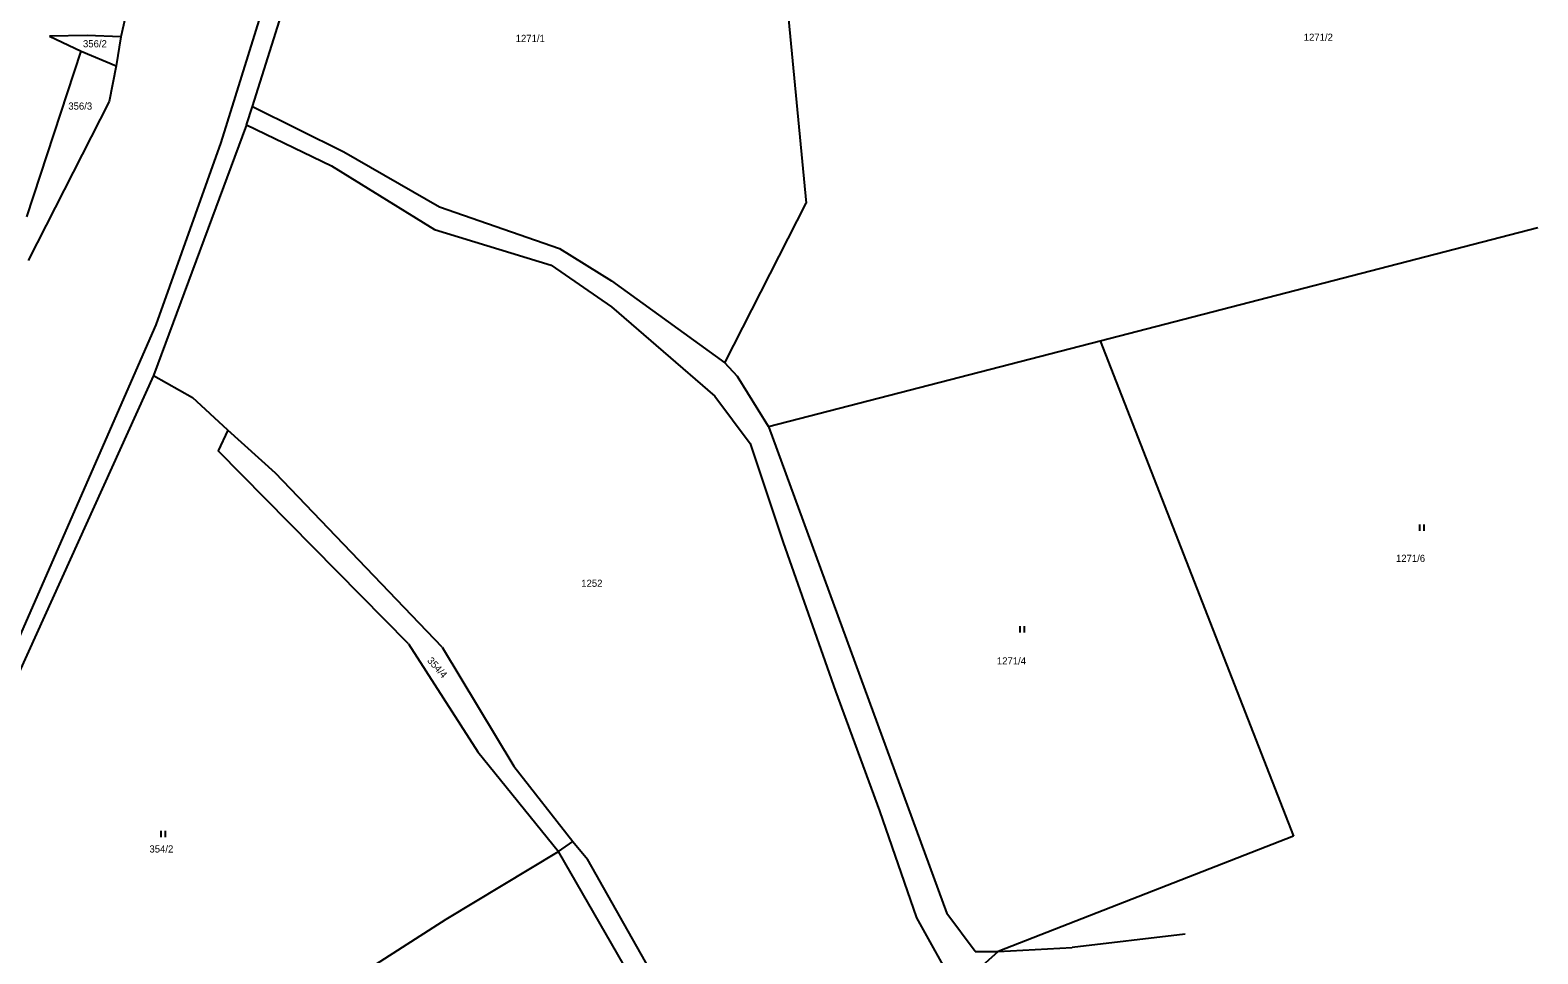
# Model space of a CAD drawing. Extents: x -717507 to -715515, y -957700 to -954941.
# Drawn here: x -716853.4 to -716494, y -957267.1 to -957047 of the extents above; entities that cross this region are included whole.
import ezdxf

# ---------------------------------------------------------------- set-up
doc = ezdxf.new("R2010")
doc.units = 0
for name, color, linetype in [('Hranice parcel', 7, 'Continuous'), ('Parcelní čísla', 7, 'Continuous'), ('Vnitřní kresba', 7, 'Continuous'), ('Značky kultur', 7, 'Continuous')]:
    doc.layers.add(name, color=color, linetype=linetype)

msp = doc.modelspace()

# ---------------------------------------------------------------- linework, layer by layer
at = {"layer": 'Hranice parcel'}
for points in [[(-716678.56, -956982.31), (-716668.42, -957088.24)], [(-716821.44, -957003.26), (-716831.73, -957048.65)], [(-716807.86, -957073.78), (-716793.1, -957026.3)], [(-716800.35, -957065.24), (-716789.3, -957030.13)], [(-716839.78, -957048.32), (-716848.77, -957048.44)], [(-716848.77, -957048.44), (-716841.23, -957052.04)], [(-716831.73, -957048.65), (-716839.78, -957048.32)], [(-716831.73, -957048.65), (-716832.89, -957055.51)], [(-716854.19, -957091.5), (-716841.23, -957052.04)], [(-716841.23, -957052.04), (-716832.89, -957055.51)], [(-716832.89, -957055.51), (-716834.54, -957064.04)], [(-716834.54, -957064.04), (-716853.87, -957101.91)], [(-716801.82, -957069.6), (-716800.35, -957065.24)], [(-716800.35, -957065.24), (-716778.59, -957076.02)], [(-716801.82, -957069.6), (-716823.97, -957129.29)], [(-716801.82, -957069.6), (-716781.58, -957079.38)], [(-716823.29, -957117.25), (-716807.86, -957073.78)], [(-716778.59, -957076.02), (-716755.82, -957089.14)], [(-716781.58, -957079.38), (-716757.02, -957094.51)], [(-716755.82, -957089.14), (-716727.24, -957099.03)], [(-716687.81, -957126.29), (-716668.42, -957088.24)], [(-716598.36, -957121.02), (-716494.03, -957094.01)], [(-716757.02, -957094.51), (-716729.16, -957103.06)], [(-716727.24, -957099.03), (-716714.82, -957106.72)], [(-716729.16, -957103.06), (-716714.79, -957112.95)], [(-716714.82, -957106.72), (-716687.81, -957126.29)], [(-716714.79, -957112.95), (-716690.17, -957134.23)], [(-716859.27, -957199.3), (-716823.29, -957117.25)], [(-716677.38, -957141.48), (-716598.36, -957121.02)], [(-716598.36, -957121.02), (-716552.25, -957239.06)], [(-716684.74, -957129.55), (-716687.81, -957126.29)], [(-716823.97, -957129.29), (-716857.93, -957204.39)], [(-716823.97, -957129.29), (-716814.69, -957134.59)], [(-716677.38, -957141.48), (-716684.74, -957129.55)], [(-716806.21, -957142.34), (-716814.69, -957134.59)], [(-716690.17, -957134.23), (-716681.72, -957145.53)], [(-716806.21, -957142.34), (-716808.59, -957147.29)], [(-716794.9, -957152.6), (-716806.21, -957142.34)], [(-716677.38, -957141.48), (-716634.86, -957257.48)], [(-716763.19, -957193.25), (-716808.59, -957147.29)], [(-716681.72, -957145.53), (-716673.91, -957169.1)], [(-716755.14, -957194.04), (-716794.9, -957152.6)], [(-716673.91, -957169.1), (-716661.46, -957204.5)], [(-716763.19, -957193.25), (-716746.65, -957219.01)], [(-716755.14, -957194.04), (-716738.11, -957222.42)], [(-716661.46, -957204.5), (-716650.97, -957233.01)], [(-716746.65, -957219.01), (-716727.45, -957242.7)], [(-716738.11, -957222.42), (-716724.03, -957240.38)], [(-716650.97, -957233.01), (-716642.15, -957258.58)], [(-716727.45, -957242.7), (-716724.03, -957240.38)], [(-716724.03, -957240.38), (-716720.49, -957244.6)], [(-716552.25, -957239.06), (-716622.66, -957266.55)], [(-716754.18, -957258.88), (-716727.45, -957242.7)], [(-716692.24, -957303.82), (-716727.45, -957242.7)], [(-716688.33, -957301.5), (-716720.49, -957244.6)], [(-716847.23, -957318.53), (-716754.18, -957258.88)], [(-716642.15, -957258.58), (-716632.66, -957275.53)], [(-716628.14, -957266.59), (-716634.86, -957257.48)], [(-716578.12, -957262.45), (-716605.01, -957265.65)], [(-716628.14, -957266.59), (-716622.66, -957266.55)], [(-716622.66, -957266.55), (-716605.01, -957265.65)]]:
    msp.add_lwpolyline(points, dxfattribs=at)
at = {"layer": 'Vnitřní kresba'}
msp.add_lwpolyline([(-716622.66, -957266.55), (-716632.66, -957275.53)], dxfattribs=at)
at = {"layer": 'Značky kultur'}
for points in [[(-716522.19, -957166.3), (-716522.19, -957164.8)], [(-716521.15, -957166.3), (-716521.15, -957164.8)], [(-716617.44, -957190.57), (-716617.44, -957189.07)], [(-716616.4, -957190.57), (-716616.4, -957189.07)], [(-716822.14, -957239.29), (-716822.14, -957237.79)], [(-716821.1, -957239.29), (-716821.1, -957237.79)]]:
    msp.add_lwpolyline(points, dxfattribs=at)

# ---------------------------------------------------------------- texts
at = {"layer": 'Parcelní čísla'}
for s, p in [('356/2', (-716840.77, -957051.11)), ('1271/1', (-716737.64, -957049.84)), ('1271/2', (-716549.83, -957049.56)), ('356/3', (-716844.27, -957065.96)), ('1271/6', (-716527.85, -957173.73)), ('1252', (-716722.02, -957179.67)), ('1271/4', (-716622.96, -957198.17)), ('354/2', (-716824.93, -957242.98))]:
    msp.add_text(s, height=1.7, dxfattribs=at).set_placement(p)
msp.add_text('354/4', height=1.7, rotation=311.8025, dxfattribs=at).set_placement((-716758.85, -957197.34))

doc.saveas('drawing.dxf')
